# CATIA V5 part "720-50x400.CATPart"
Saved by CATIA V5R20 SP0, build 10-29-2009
Part number: 720-50x400
Definition: NONE
Nomenclature: 720-50x400
Source: Unknown
Description: 720-50x400
Bounding box of the stored display mesh (mm): x 0 to 400, y -25 to 25, z -25 to 25
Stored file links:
  C:\Users\Utente\Desktop\IO LAVORO\3D X SITO CF\X SITO\720\720-50x400.CATPart
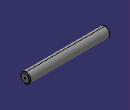
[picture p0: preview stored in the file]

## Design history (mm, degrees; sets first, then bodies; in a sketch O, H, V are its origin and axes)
Body1 "720-50x400" (main body)
  Solid1: solid without history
